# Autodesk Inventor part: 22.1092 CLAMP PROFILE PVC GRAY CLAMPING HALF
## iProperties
Created: 2007-04
Part Number: 22.1092 CLAMP PROFILE PVC GRAY CLAMPING HALF
Material: PVC-U
Document SubType Name: Modeling
Designer: Andy Moles
Density: 1.4 g/cm^3
Author: Andy Moles
